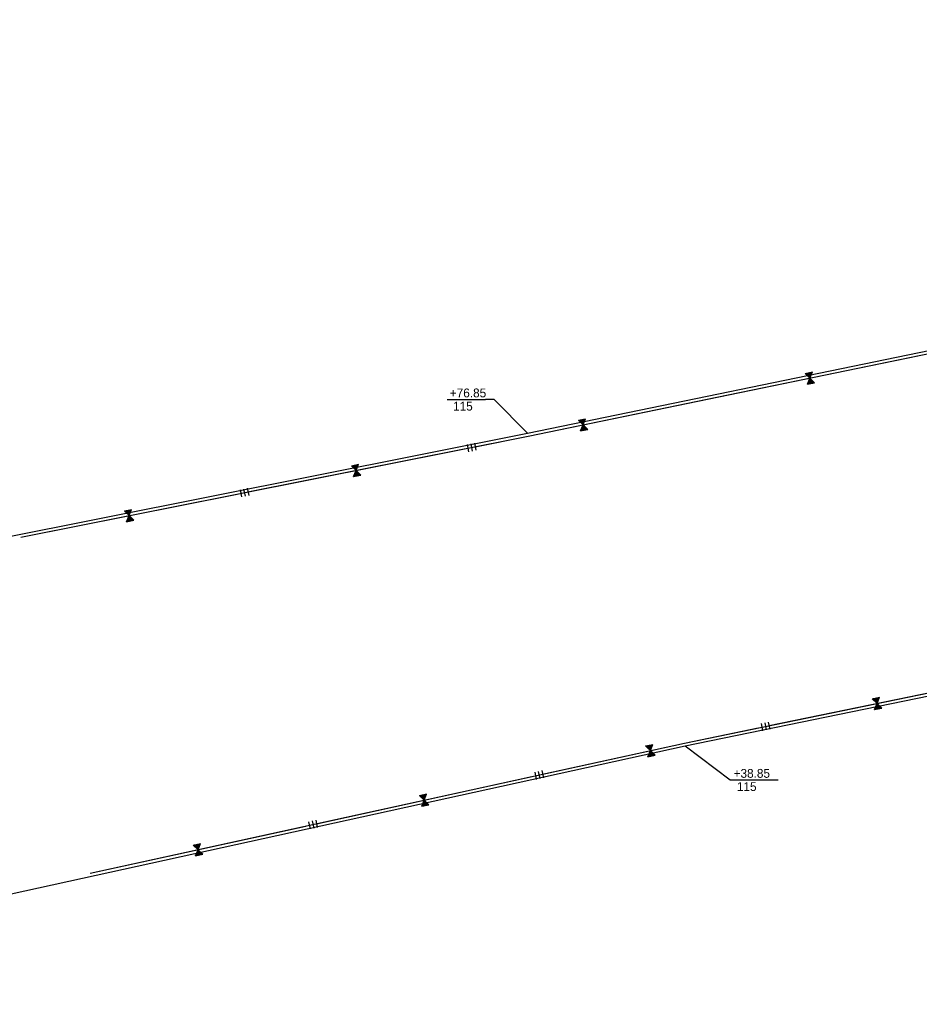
# Model space of a CAD drawing. Extents: x 979729 to 993523, y 1834148 to 1845433.
# Drawn here: x 986865 to 987477, y 1838037 to 1838707 of the extents above; entities that cross this region are included whole.
import ezdxf

# ---------------------------------------------------------------- set-up
doc = ezdxf.new("R2010")
doc.units = 0
for name, color, linetype in [('42', 7, 'Continuous'), ('51', 7, 'Continuous'), ('R_Draft', 7, 'Continuous')]:
    doc.layers.add(name, color=color, linetype=linetype)

msp = doc.modelspace()

# ---------------------------------------------------------------- linework, layer by layer
at = {"layer": '42'}
for p, q in [((987210.55, 1838424.02), (987894.28, 1838565.17)), ((987401.33, 1838464.42), (987402.57, 1838467.49)), ((987401.53, 1838464.25), (987402.86, 1838467.55)), ((987401.71, 1838464.04), (987403.16, 1838467.61)), ((987401.92, 1838463.9), (987403.45, 1838467.67)), ((987402.1, 1838463.66), (987403.74, 1838467.74)), ((987402.15, 1838463.58), (987403.84, 1838467.76)), ((987398.95, 1838466.74), (987402.15, 1838463.58)), ((987399.01, 1838466.7), (987399.04, 1838466.76)), ((987399.21, 1838466.53), (987399.33, 1838466.82)), ((987399.4, 1838466.32), (987399.63, 1838466.88)), ((987399.6, 1838466.15), (987399.92, 1838466.95)), ((987399.78, 1838465.94), (987400.21, 1838467.01)), ((987399.97, 1838465.73), (987400.51, 1838467.07)), ((987400.17, 1838465.56), (987400.8, 1838467.13)), ((987400.39, 1838465.45), (987401.03, 1838467.03)), ((987400.46, 1838459.4), (987402.15, 1838463.58)), ((987400.57, 1838465.21), (987401.39, 1838467.25)), ((987400.77, 1838465.04), (987401.69, 1838467.31)), ((987400.94, 1838464.8), (987401.98, 1838467.37)), ((987401.12, 1838460.97), (987402.32, 1838459.78)), ((987401.15, 1838464.66), (987402.27, 1838467.43)), ((987401.28, 1838461.16), (987402.49, 1838459.96)), ((987401.34, 1838461.45), (987402.91, 1838459.9)), ((987401.46, 1838461.69), (987403.2, 1838459.97)), ((987401.52, 1838461.97), (987403.5, 1838460.03)), ((987401.66, 1838462.19), (987403.79, 1838460.09)), ((987401.73, 1838462.48), (987404.08, 1838460.15)), ((987401.84, 1838462.71), (987404.38, 1838460.21)), ((987401.93, 1838462.98), (987404.67, 1838460.27)), ((987402.07, 1838463.19), (987404.97, 1838460.33)), ((987402.13, 1838463.48), (987405.26, 1838460.39)), ((987402.15, 1838463.58), (987405.36, 1838460.41)), ((987400.51, 1838459.46), (987400.55, 1838459.42)), ((987400.62, 1838459.7), (987400.85, 1838459.48)), ((987400.71, 1838459.97), (987401.14, 1838459.54)), ((987400.83, 1838460.2), (987401.44, 1838459.6)), ((987400.91, 1838460.47), (987401.73, 1838459.66)), ((987401, 1838460.73), (987402.03, 1838459.72)), ((987244.7, 1838434.9), (987247.9, 1838431.73)), ((987244.77, 1838434.86), (987244.79, 1838434.92)), ((987244.97, 1838434.69), (987245.08, 1838434.98)), ((987245.15, 1838434.48), (987245.38, 1838435.04)), ((987245.35, 1838434.31), (987245.67, 1838435.1)), ((987245.54, 1838434.1), (987245.97, 1838435.16)), ((987245.72, 1838433.89), (987246.26, 1838435.22)), ((987245.92, 1838433.72), (987246.56, 1838435.28)), ((987246.15, 1838433.61), (987246.79, 1838435.19)), ((987246.32, 1838433.36), (987247.14, 1838435.41)), ((987246.52, 1838433.19), (987247.44, 1838435.47)), ((987246.69, 1838432.96), (987247.73, 1838435.53)), ((987246.9, 1838432.81), (987248.03, 1838435.59)), ((987247.08, 1838432.58), (987248.32, 1838435.65)), ((987247.28, 1838432.41), (987248.61, 1838435.71)), ((987247.46, 1838432.2), (987248.91, 1838435.77)), ((987247.67, 1838432.05), (987249.2, 1838435.83)), ((987247.85, 1838431.82), (987249.5, 1838435.89)), ((987247.9, 1838431.73), (987249.6, 1838435.91)), ((987246.21, 1838427.56), (987247.9, 1838431.73)), ((987246.26, 1838427.62), (987246.31, 1838427.58)), ((987246.38, 1838427.86), (987246.6, 1838427.64)), ((987246.46, 1838428.12), (987246.89, 1838427.7)), ((987246.58, 1838428.36), (987247.19, 1838427.76)), ((987246.67, 1838428.63), (987247.48, 1838427.82)), ((987246.75, 1838428.89), (987247.78, 1838427.88)), ((987246.87, 1838429.13), (987248.07, 1838427.94)), ((987247.03, 1838429.32), (987248.25, 1838428.12)), ((987247.09, 1838429.61), (987248.66, 1838428.06)), ((987247.21, 1838429.85), (987248.95, 1838428.12)), ((987247.28, 1838430.13), (987249.25, 1838428.18)), ((987247.41, 1838430.35), (987249.54, 1838428.24)), ((987247.48, 1838430.63), (987249.84, 1838428.3)), ((987247.6, 1838430.87), (987250.13, 1838428.36)), ((987247.68, 1838431.13), (987250.42, 1838428.43)), ((987247.82, 1838431.35), (987250.72, 1838428.49)), ((987247.89, 1838431.64), (987251.01, 1838428.55)), ((987247.9, 1838431.73), (987251.11, 1838428.57)), ((986865.46, 1838355.36), (987210.55, 1838424.02)), ((987169.01, 1838418.31), (987169.99, 1838413.4)), ((987171.46, 1838418.79), (987172.44, 1838413.89)), ((987173.91, 1838419.28), (987174.89, 1838414.38)), ((987090.3, 1838403.92), (987093.49, 1838400.73)), ((987090.37, 1838403.88), (987090.39, 1838403.94)), ((987090.57, 1838403.71), (987090.69, 1838404)), ((987090.75, 1838403.49), (987090.98, 1838404.06)), ((987090.95, 1838403.32), (987091.28, 1838404.11)), ((987091.14, 1838403.11), (987091.57, 1838404.17)), ((987091.32, 1838402.9), (987091.87, 1838404.23)), ((987091.52, 1838402.73), (987092.16, 1838404.29)), ((987091.74, 1838402.62), (987092.39, 1838404.2)), ((987091.77, 1838396.56), (987093.49, 1838400.73)), ((987091.91, 1838402.37), (987092.75, 1838404.41)), ((987092.11, 1838402.2), (987093.05, 1838404.47)), ((987092.28, 1838401.96), (987093.34, 1838404.52)), ((987092.49, 1838401.82), (987093.64, 1838404.58)), ((987092.67, 1838401.58), (987093.93, 1838404.64)), ((987092.87, 1838401.41), (987094.23, 1838404.7)), ((987093.05, 1838401.2), (987094.52, 1838404.76)), ((987093.26, 1838401.05), (987094.82, 1838404.82)), ((987093.43, 1838400.81), (987095.11, 1838404.88)), ((987093.47, 1838400.63), (987096.57, 1838397.52)), ((987093.49, 1838400.73), (987095.21, 1838404.9)), ((987093.49, 1838400.73), (987096.67, 1838397.54)), ((987091.81, 1838396.63), (987091.86, 1838396.58)), ((987091.93, 1838396.86), (987092.15, 1838396.64)), ((987092.02, 1838397.13), (987092.45, 1838396.7)), ((987092.14, 1838397.36), (987092.74, 1838396.76)), ((987092.23, 1838397.63), (987093.04, 1838396.82)), ((987092.32, 1838397.89), (987093.33, 1838396.88)), ((987092.43, 1838398.13), (987093.63, 1838396.93)), ((987092.6, 1838398.32), (987093.8, 1838397.11)), ((987092.66, 1838398.61), (987094.22, 1838397.05)), ((987092.78, 1838398.85), (987094.51, 1838397.11)), ((987092.85, 1838399.13), (987094.81, 1838397.17)), ((987092.99, 1838399.35), (987095.1, 1838397.23)), ((987093.05, 1838399.63), (987095.4, 1838397.29)), ((987093.17, 1838399.87), (987095.69, 1838397.34)), ((987093.26, 1838400.13), (987095.98, 1838397.4)), ((987093.4, 1838400.35), (987096.28, 1838397.46)), ((987014.54, 1838387.57), (987015.51, 1838382.67)), ((987016.99, 1838388.06), (987017.97, 1838383.15)), ((987019.44, 1838388.55), (987020.42, 1838383.64)), ((986937.44, 1838371.63), (986938.28, 1838373.67)), ((986937.64, 1838371.46), (986938.58, 1838373.73)), ((986937.81, 1838371.23), (986938.87, 1838373.79)), ((986938.02, 1838371.08), (986939.17, 1838373.85)), ((986938.2, 1838370.84), (986939.46, 1838373.91)), ((986938.39, 1838370.67), (986939.75, 1838373.96)), ((986938.58, 1838370.46), (986940.05, 1838374.02)), ((986938.79, 1838370.31), (986940.34, 1838374.08)), ((986938.96, 1838370.08), (986940.64, 1838374.14)), ((986939.02, 1838369.99), (986940.74, 1838374.16)), ((986935.83, 1838373.18), (986939.02, 1838369.99)), ((986935.9, 1838373.14), (986935.92, 1838373.2)), ((986936.1, 1838372.97), (986936.22, 1838373.26)), ((986936.28, 1838372.76), (986936.51, 1838373.32)), ((986936.48, 1838372.59), (986936.81, 1838373.38)), ((986936.66, 1838372.38), (986937.1, 1838373.44)), ((986936.85, 1838372.17), (986937.4, 1838373.5)), ((986937.05, 1838371.99), (986937.69, 1838373.55)), ((986937.27, 1838371.88), (986937.92, 1838373.46)), ((986937.3, 1838365.83), (986939.02, 1838369.99)), ((986937.84, 1838367.16), (986938.86, 1838366.14)), ((986937.96, 1838367.39), (986939.16, 1838366.2)), ((986938.12, 1838367.58), (986939.33, 1838366.37)), ((986938.19, 1838367.87), (986939.74, 1838366.32)), ((986938.31, 1838368.11), (986940.04, 1838366.37)), ((986938.38, 1838368.39), (986940.33, 1838366.43)), ((986938.51, 1838368.61), (986940.63, 1838366.49)), ((986938.58, 1838368.9), (986940.92, 1838366.55)), ((986938.7, 1838369.13), (986941.22, 1838366.61)), ((986938.79, 1838369.39), (986941.51, 1838366.67)), ((986938.93, 1838369.61), (986941.81, 1838366.73)), ((986939, 1838369.9), (986942.1, 1838366.78)), ((986939.02, 1838369.99), (986942.2, 1838366.8)), ((986937.34, 1838365.89), (986937.39, 1838365.85)), ((986937.46, 1838366.13), (986937.68, 1838365.9)), ((986937.55, 1838366.39), (986937.98, 1838365.96)), ((986937.67, 1838366.63), (986938.27, 1838366.02)), ((986937.75, 1838366.89), (986938.57, 1838366.08)), ((987316.96, 1838215.23), (987939.98, 1838343.84)), ((987447.77, 1838242.32), (987449.42, 1838246.4)), ((987447.82, 1838242.24), (987449.51, 1838246.42)), ((987444.62, 1838245.41), (987447.82, 1838242.24)), ((987444.68, 1838245.37), (987444.71, 1838245.43)), ((987444.88, 1838245.19), (987445, 1838245.49)), ((987445.07, 1838244.98), (987445.3, 1838245.55)), ((987445.27, 1838244.81), (987445.59, 1838245.61)), ((987445.45, 1838244.61), (987445.89, 1838245.67)), ((987445.64, 1838244.4), (987446.18, 1838245.73)), ((987445.84, 1838244.23), (987446.47, 1838245.79)), ((987446.06, 1838244.11), (987446.71, 1838245.7)), ((987446.13, 1838238.06), (987447.82, 1838242.24)), ((987446.24, 1838243.87), (987447.06, 1838245.91)), ((987446.44, 1838243.7), (987447.36, 1838245.97)), ((987446.61, 1838243.46), (987447.65, 1838246.03)), ((987446.82, 1838243.32), (987447.95, 1838246.09)), ((987446.95, 1838239.82), (987448.17, 1838238.62)), ((987447, 1838243.08), (987448.24, 1838246.16)), ((987447.01, 1838240.12), (987448.58, 1838238.57)), ((987447.13, 1838240.35), (987448.87, 1838238.63)), ((987447.19, 1838240.64), (987449.17, 1838238.69)), ((987447.2, 1838242.91), (987448.53, 1838246.22)), ((987447.33, 1838240.85), (987449.46, 1838238.75)), ((987447.38, 1838242.7), (987448.83, 1838246.28)), ((987447.4, 1838241.14), (987449.76, 1838238.81)), ((987447.51, 1838241.37), (987450.05, 1838238.87)), ((987447.59, 1838242.56), (987449.12, 1838246.34)), ((987447.6, 1838241.64), (987450.34, 1838238.93)), ((987447.74, 1838241.86), (987450.64, 1838238.99)), ((987447.8, 1838242.14), (987450.93, 1838239.05)), ((987447.82, 1838242.24), (987451.03, 1838239.07)), ((987446.18, 1838238.13), (987446.22, 1838238.08)), ((987446.29, 1838238.36), (987446.52, 1838238.14)), ((987446.38, 1838238.63), (987446.81, 1838238.2)), ((987446.5, 1838238.87), (987447.11, 1838238.26)), ((987446.58, 1838239.13), (987447.4, 1838238.32)), ((987446.67, 1838239.39), (987447.7, 1838238.38)), ((987446.79, 1838239.63), (987447.99, 1838238.45)), ((987368.97, 1838228.51), (987369.98, 1838223.62)), ((987371.42, 1838229.02), (987372.43, 1838224.12)), ((987373.87, 1838229.53), (987374.88, 1838224.63)), ((986912.68, 1838126.61), (987316.95, 1838215.22)), ((987290.39, 1838213.24), (987293.64, 1838210.11)), ((987290.46, 1838213.2), (987290.48, 1838213.26)), ((987290.66, 1838213.03), (987290.78, 1838213.32)), ((987290.85, 1838212.82), (987291.07, 1838213.39)), ((987291.05, 1838212.66), (987291.36, 1838213.45)), ((987291.24, 1838212.45), (987291.66, 1838213.52)), ((987291.43, 1838212.24), (987291.95, 1838213.58)), ((987291.63, 1838212.07), (987292.24, 1838213.65)), ((987291.85, 1838211.96), (987292.48, 1838213.56)), ((987292.03, 1838211.72), (987292.83, 1838213.77)), ((987292.23, 1838211.55), (987293.12, 1838213.84)), ((987292.41, 1838211.32), (987293.42, 1838213.9)), ((987292.62, 1838211.18), (987293.71, 1838213.97)), ((987292.8, 1838210.95), (987294, 1838214.03)), ((987293, 1838210.78), (987294.3, 1838214.1)), ((987293.19, 1838210.57), (987294.59, 1838214.16)), ((987293.4, 1838210.43), (987294.88, 1838214.23)), ((987293.58, 1838210.2), (987295.18, 1838214.29)), ((987293.64, 1838210.11), (987295.28, 1838214.31)), ((987292, 1838205.91), (987293.64, 1838210.11)), ((987292.16, 1838206.22), (987292.38, 1838206)), ((987292.24, 1838206.48), (987292.68, 1838206.06)), ((987292.35, 1838206.72), (987292.97, 1838206.13)), ((987292.44, 1838206.99), (987293.26, 1838206.19)), ((987292.52, 1838207.25), (987293.56, 1838206.26)), ((987292.63, 1838207.49), (987293.85, 1838206.32)), ((987292.79, 1838207.69), (987294.02, 1838206.5)), ((987292.85, 1838207.98), (987294.44, 1838206.45)), ((987292.96, 1838208.22), (987294.73, 1838206.51)), ((987293.03, 1838208.5), (987295.02, 1838206.58)), ((987293.16, 1838208.72), (987295.32, 1838206.64)), ((987293.22, 1838209.01), (987295.61, 1838206.71)), ((987293.34, 1838209.24), (987295.9, 1838206.77)), ((987293.42, 1838209.51), (987296.2, 1838206.83)), ((987293.55, 1838209.73), (987296.49, 1838206.9)), ((987293.62, 1838210.01), (987296.78, 1838206.96)), ((987293.64, 1838210.11), (987296.88, 1838206.98)), ((987292.04, 1838205.98), (987292.09, 1838205.93)), ((987214.96, 1838195.43), (987216.03, 1838190.54)), ((987217.4, 1838195.96), (987218.47, 1838191.08)), ((987219.84, 1838196.5), (987220.91, 1838191.61)), ((987136.54, 1838179.52), (987139.79, 1838176.39)), ((987136.61, 1838179.48), (987136.63, 1838179.54)), ((987136.81, 1838179.31), (987136.93, 1838179.6)), ((987137, 1838179.1), (987137.22, 1838179.67)), ((987137.2, 1838178.93), (987137.52, 1838179.73)), ((987137.39, 1838178.73), (987137.81, 1838179.8)), ((987137.58, 1838178.52), (987138.1, 1838179.86)), ((987137.78, 1838178.35), (987138.4, 1838179.92)), ((987138.01, 1838178.24), (987138.63, 1838179.83)), ((987138.18, 1838178), (987138.98, 1838180.05)), ((987138.38, 1838177.83), (987139.28, 1838180.12)), ((987138.56, 1838177.6), (987139.57, 1838180.18)), ((987138.77, 1838177.46), (987139.86, 1838180.25)), ((987138.95, 1838177.22), (987140.16, 1838180.31)), ((987139.15, 1838177.06), (987140.45, 1838180.38)), ((987139.34, 1838176.85), (987140.74, 1838180.44)), ((987139.55, 1838176.71), (987141.04, 1838180.5)), ((987139.73, 1838176.47), (987141.33, 1838180.57)), ((987139.79, 1838176.39), (987141.43, 1838180.59)), ((987138.15, 1838172.19), (987139.79, 1838176.39)), ((987138.39, 1838172.76), (987138.83, 1838172.34)), ((987138.5, 1838173), (987139.12, 1838172.41)), ((987138.59, 1838173.27), (987139.41, 1838172.47)), ((987138.67, 1838173.53), (987139.71, 1838172.53)), ((987138.79, 1838173.77), (987140, 1838172.6)), ((987138.94, 1838173.96), (987140.18, 1838172.78)), ((987139, 1838174.26), (987140.59, 1838172.73)), ((987139.12, 1838174.49), (987140.88, 1838172.79)), ((987139.18, 1838174.78), (987141.18, 1838172.86)), ((987139.31, 1838175), (987141.47, 1838172.92)), ((987139.38, 1838175.28), (987141.76, 1838172.98)), ((987139.49, 1838175.52), (987142.06, 1838173.05)), ((987139.57, 1838175.79), (987142.35, 1838173.11)), ((987139.71, 1838176.01), (987142.64, 1838173.18)), ((987139.77, 1838176.29), (987142.94, 1838173.24)), ((987139.79, 1838176.39), (987143.03, 1838173.26)), ((987138.19, 1838172.26), (987138.24, 1838172.21)), ((987138.31, 1838172.5), (987138.53, 1838172.28)), ((987061.11, 1838161.7), (987062.18, 1838156.82)), ((987063.55, 1838162.24), (987064.62, 1838157.36)), ((987065.99, 1838162.78), (987067.06, 1838157.89)), ((986983.15, 1838145.38), (986983.37, 1838145.95)), ((986983.36, 1838145.21), (986983.67, 1838146.01)), ((986983.54, 1838145.01), (986983.96, 1838146.07)), ((986983.73, 1838144.8), (986984.26, 1838146.14)), ((986983.93, 1838144.63), (986984.55, 1838146.2)), ((986984.16, 1838144.52), (986984.78, 1838146.11)), ((986984.33, 1838144.28), (986985.14, 1838146.33)), ((986984.54, 1838144.11), (986985.43, 1838146.4)), ((986984.71, 1838143.88), (986985.72, 1838146.46)), ((986984.93, 1838143.74), (986986.02, 1838146.53)), ((986985.1, 1838143.5), (986986.31, 1838146.59)), ((986985.31, 1838143.34), (986986.6, 1838146.65)), ((986985.49, 1838143.13), (986986.9, 1838146.72)), ((986985.71, 1838142.98), (986987.19, 1838146.78)), ((986985.88, 1838142.75), (986987.48, 1838146.85)), ((986985.94, 1838142.67), (986987.58, 1838146.87)), ((986982.7, 1838145.8), (986985.94, 1838142.67)), ((986982.76, 1838145.76), (986982.79, 1838145.82)), ((986982.97, 1838145.59), (986983.08, 1838145.88)), ((986984.3, 1838138.47), (986985.94, 1838142.67)), ((986984.66, 1838139.28), (986985.27, 1838138.68)), ((986984.74, 1838139.55), (986985.57, 1838138.75)), ((986984.83, 1838139.81), (986985.86, 1838138.81)), ((986984.94, 1838140.05), (986986.15, 1838138.88)), ((986985.1, 1838140.24), (986986.33, 1838139.06)), ((986985.15, 1838140.54), (986986.74, 1838139.01)), ((986985.27, 1838140.77), (986987.04, 1838139.07)), ((986985.33, 1838141.06), (986987.33, 1838139.13)), ((986985.47, 1838141.28), (986987.62, 1838139.2)), ((986985.53, 1838141.56), (986987.92, 1838139.26)), ((986985.64, 1838141.8), (986988.21, 1838139.33)), ((986985.73, 1838142.07), (986988.5, 1838139.39)), ((986985.86, 1838142.29), (986988.8, 1838139.46)), ((986985.92, 1838142.57), (986989.09, 1838139.52)), ((986985.94, 1838142.67), (986989.19, 1838139.54)), ((986984.35, 1838138.54), (986984.39, 1838138.49)), ((986984.46, 1838138.78), (986984.69, 1838138.56)), ((986984.54, 1838139.04), (986984.98, 1838138.62))]:
    msp.add_line(p, q, dxfattribs=at)
for points in [[(987338.89, 1838450.52), (987475.6, 1838478.74)], [(987398.95, 1838466.74), (987403.84, 1838467.76)], [(987400.46, 1838459.4), (987405.36, 1838460.41)], [(987174.4, 1838416.83), (987210.55, 1838424.02), (987210.55, 1838424.02), (987338.89, 1838450.52)], [(987244.7, 1838434.9), (987249.6, 1838435.91)], [(987246.21, 1838427.56), (987251.11, 1838428.57)], [(987019.93, 1838386.09), (987167.05, 1838415.37)], [(987090.3, 1838403.92), (987095.21, 1838404.9)], [(987091.77, 1838396.56), (987096.67, 1838397.54)], [(986865.46, 1838355.36), (987012.57, 1838384.63)], [(986935.83, 1838373.18), (986940.74, 1838374.16)], [(986937.3, 1838365.83), (986942.2, 1838366.8)], [(987374.37, 1838227.08), (987521.27, 1838257.4)], [(987444.62, 1838245.41), (987449.51, 1838246.42)], [(987446.13, 1838238.06), (987451.03, 1838239.07)], [(987220.38, 1838194.05), (987316.95, 1838215.22), (987316.96, 1838215.23), (987367.03, 1838225.56)], [(987290.39, 1838213.24), (987295.28, 1838214.31)], [(987292, 1838205.91), (987296.88, 1838206.98)], [(987066.53, 1838160.33), (987213.05, 1838192.45)], [(987136.54, 1838179.52), (987141.43, 1838180.59)], [(987138.15, 1838172.19), (987143.03, 1838173.26)], [(986912.68, 1838126.61), (987059.2, 1838158.73)], [(986982.7, 1838145.8), (986987.58, 1838146.87)], [(986984.3, 1838138.47), (986989.19, 1838139.54)]]:
    msp.add_lwpolyline(points, dxfattribs=at)
at = {"layer": '51'}
for p, q in [((987210.15, 1838425.98), (988573.1, 1838707.35)), ((987317.37, 1838213.27), (988564.68, 1838470.76)), ((986526.26, 1838289.91), (987210.15, 1838425.98)), ((986515.41, 1838037.5), (987317.37, 1838213.27))]:
    msp.add_line(p, q, dxfattribs=at)
at = {"layer": 'R_Draft'}
for p, q in [((987155.43, 1838448.92), (987181.47, 1838448.92)), ((987353.89, 1838190.11), (987380.47, 1838190.11))]:
    msp.add_line(p, q, dxfattribs=at)
for points in [[(987210.15, 1838425.98), (987187.47, 1838448.92), (987181.47, 1838448.92)], [(987317.37, 1838213.27), (987347.89, 1838190.11), (987353.89, 1838190.11)]]:
    msp.add_lwpolyline(points, dxfattribs=at)

# ---------------------------------------------------------------- texts
for s, p in [('+76.85', (987157.2, 1838450.42)), (' 115', (987157.2, 1838441.42)), ('+38.85', (987350.26, 1838191.61)), (' 115', (987350.26, 1838182.61))]:
    msp.add_text(s, height=6, rotation=360, dxfattribs=at).set_placement(p)

doc.saveas('drawing.dxf')
